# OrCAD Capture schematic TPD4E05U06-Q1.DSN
size A; title: TPD4E05U06-Q1 4 Channel Protection Solution for Super-Speed Interface; rev: 1.0; note: Datasheet: SLVSCO7C
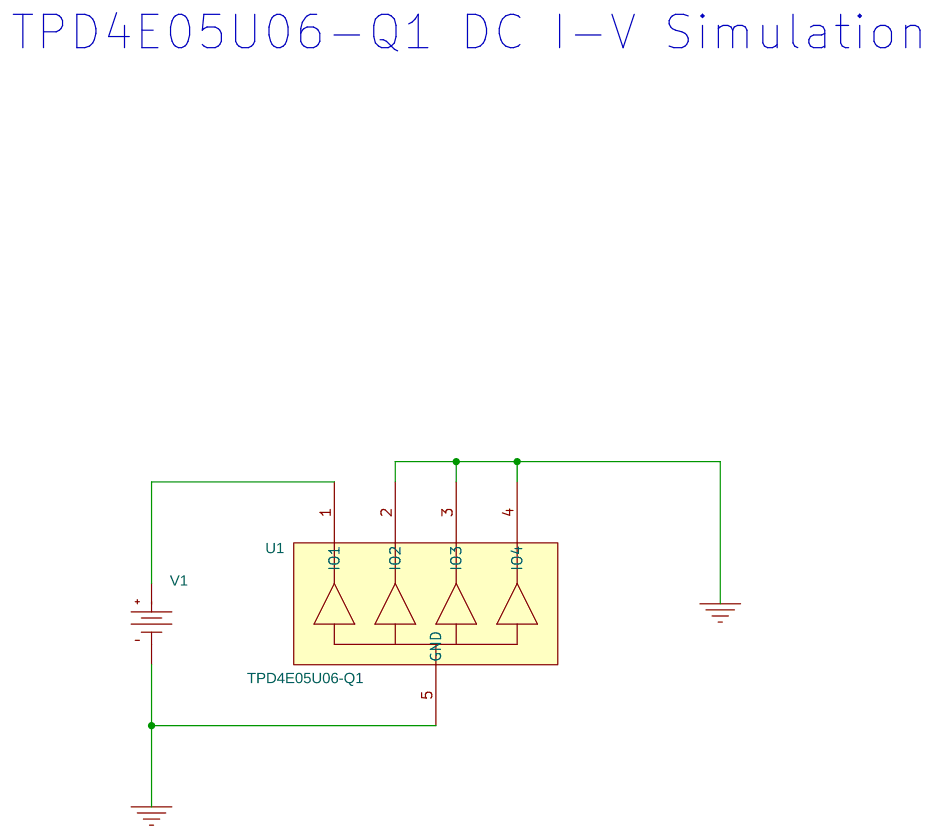
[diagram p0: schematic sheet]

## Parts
U1  TPD4E05U06-Q1
V1  VDC

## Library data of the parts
U1 = TPD4E05U06-Q1
V1 = VDC

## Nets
0: U1.2(IO2) U1.3(IO3) U1.4(IO4) U1.5(GND) V1.1(-)
N03229: U1.1(IO1) V1.0(+)

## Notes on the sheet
- TPD4E05U06-Q1 DC I-V Simulation
